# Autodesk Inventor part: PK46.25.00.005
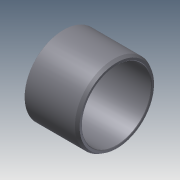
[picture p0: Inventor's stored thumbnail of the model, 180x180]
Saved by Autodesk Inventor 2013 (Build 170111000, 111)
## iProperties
Created: 2005-05
Part Number: PK46.25.00.005
Material: Steel, Mild
Document SubType Name: Modeling
Designer: PVitaliy
Manufacturer: Standard
Standards Organization: Custom
Density: 7.86 g/cm^3
Mass: 642.301 g
Surface Area: 351.265 cm^2
Volume: 81.7177 cm^3
Author: PVitaliy
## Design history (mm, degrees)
sketch "Эскиз2"
  geometry: L1 (0, 0)-(45.09, 0); L2 (0, 45)-(58.536, 45); L3 (0, 45)-(0, 40); L4 (0, 40)-(62, 40); L5 (62, 40)-(62, 43); L6 (58.536, 45)-(62, 43)
  constraints: 12 end point, 3 horizontal, 2 vertical, 1 point on line, 1 other
  dimensions: "d0" = 90 diameter of L2 L1; "d1" = 80 diameter of L4 L1; "d3" = 62 distance of L3.end L4.end; "d4" = 30 deg angle of L6 L2; "d5" = 86 diameter of L5.end L1
revolve "Вращение1" sketch "Эскиз2" stored, may be unused: angle "d6" = 90 deg
chamfer "Фаска1" distance "d7" = 0.5; stored, may be unused: second distance "d8" = 2, angle "d9" = 45 deg
body "Solid1"
